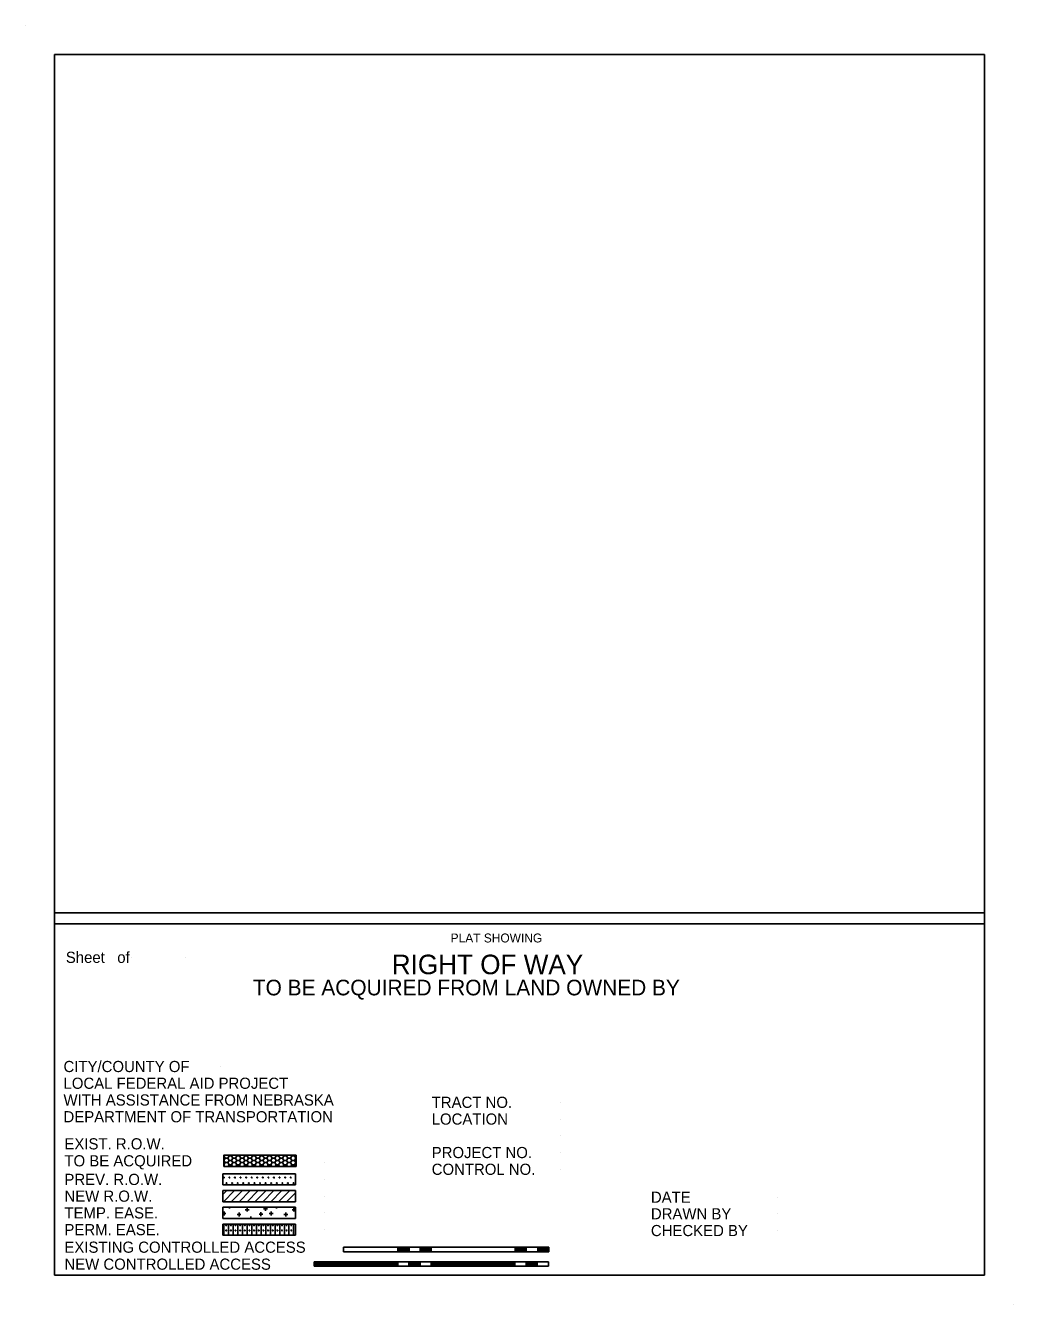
# Model space of a CAD drawing. Extents: x 18533 to 19383, y 1281 to 2381.
import ezdxf

# ---------------------------------------------------------------- set-up
doc = ezdxf.new("R2010")
doc.units = 0
doc.layers.add('Level 42', color=7, linetype='Continuous')

msp = doc.modelspace()

# ---------------------------------------------------------------- linework, layer by layer
at = {"layer": 'Level 42'}
for p, q in [((18532.7, 2381.3), (18532.7, 2381.3)), ((18557.7, 1306.4), (18557.7, 2356.3)), ((18557.7, 2356.3), (19357.7, 2356.3)), ((19357.7, 2356.3), (19357.7, 1306.4)), ((18557.7, 1618.3), (19357.7, 1618.3)), ((18557.7, 1608.7), (19357.7, 1608.7)), ((18624, 1579.9), (18624, 1579.9)), ((18670.7, 1579.9), (18670.7, 1579.9)), ((18700.8, 1486), (18700.8, 1486)), ((18993, 1455.2), (18993, 1455.2)), ((18993, 1440.8), (18993, 1440.8)), ((18993, 1426.4), (18993, 1426.4)), ((18703.2, 1409.7), (18703.2, 1400.1)), ((18703.2, 1409.7), (18765.6, 1409.7)), ((18703.2, 1409.1), (18703.3, 1409.1)), ((18703.6, 1409.7), (18703.3, 1409.1)), ((18703.3, 1409.1), (18704.4, 1407.2)), ((18707.8, 1409.1), (18706.7, 1407.2)), ((18707.4, 1409.7), (18707.8, 1409.1)), ((18707.8, 1409.1), (18710, 1409.1)), ((18710.4, 1409.7), (18710, 1409.1)), ((18710, 1409.1), (18711.2, 1407.2)), ((18714.5, 1409.1), (18713.4, 1407.2)), ((18714.2, 1409.7), (18714.5, 1409.1)), ((18714.5, 1409.1), (18716.8, 1409.1)), ((18717.1, 1409.7), (18716.8, 1409.1)), ((18716.8, 1409.1), (18717.9, 1407.2)), ((18721.3, 1409.1), (18720.2, 1407.2)), ((18720.9, 1409.7), (18721.3, 1409.1)), ((18721.3, 1409.1), (18723.5, 1409.1)), ((18723.9, 1409.7), (18723.5, 1409.1)), ((18723.5, 1409.1), (18724.7, 1407.2)), ((18728, 1409.1), (18726.9, 1407.2)), ((18727.7, 1409.7), (18728, 1409.1)), ((18728, 1409.1), (18730.3, 1409.1)), ((18730.6, 1409.7), (18730.3, 1409.1)), ((18730.3, 1409.1), (18731.4, 1407.2)), ((18734.8, 1409.1), (18733.7, 1407.2)), ((18734.4, 1409.7), (18734.8, 1409.1)), ((18734.8, 1409.1), (18737, 1409.1)), ((18737.4, 1409.7), (18737, 1409.1)), ((18737, 1409.1), (18738.2, 1407.2)), ((18741.5, 1409.1), (18740.4, 1407.2)), ((18741.2, 1409.7), (18741.5, 1409.1)), ((18741.5, 1409.1), (18743.8, 1409.1)), ((18744.1, 1409.7), (18743.8, 1409.1)), ((18743.8, 1409.1), (18744.9, 1407.2)), ((18748.3, 1409.1), (18747.2, 1407.2)), ((18747.9, 1409.7), (18748.3, 1409.1)), ((18748.3, 1409.1), (18750.5, 1409.1)), ((18750.9, 1409.7), (18750.5, 1409.1)), ((18750.5, 1409.1), (18751.7, 1407.2)), ((18755, 1409.1), (18753.9, 1407.2)), ((18754.7, 1409.7), (18755, 1409.1)), ((18755, 1409.1), (18757.3, 1409.1)), ((18757.6, 1409.7), (18757.3, 1409.1)), ((18757.3, 1409.1), (18758.4, 1407.2)), ((18761.8, 1409.1), (18760.7, 1407.2)), ((18761.4, 1409.7), (18761.8, 1409.1)), ((18761.8, 1409.1), (18764, 1409.1)), ((18764.4, 1409.7), (18764, 1409.1)), ((18764, 1409.1), (18765.2, 1407.2)), ((18765.6, 1409.7), (18765.6, 1400.1)), ((18993, 1412), (18993, 1412)), ((18703.2, 1405.2), (18703.3, 1405.2)), ((18703.2, 1401.3), (18703.3, 1401.3)), ((18703.2, 1400.1), (18765.6, 1400.1)), ((18704.4, 1407.2), (18703.3, 1405.2)), ((18703.3, 1405.2), (18704.4, 1403.3)), ((18704.4, 1403.3), (18703.3, 1401.3)), ((18703.3, 1401.3), (18704, 1400.1)), ((18704.4, 1407.2), (18706.7, 1407.2)), ((18704.4, 1403.3), (18706.7, 1403.3)), ((18706.7, 1407.2), (18707.8, 1405.2)), ((18707.8, 1405.2), (18706.7, 1403.3)), ((18706.7, 1403.3), (18707.8, 1401.3)), ((18707.1, 1400.1), (18707.8, 1401.3)), ((18707.8, 1405.2), (18710, 1405.2)), ((18707.8, 1401.3), (18710, 1401.3)), ((18711.2, 1407.2), (18710, 1405.2)), ((18710, 1405.2), (18711.2, 1403.3)), ((18711.2, 1403.3), (18710, 1401.3)), ((18710, 1401.3), (18710.7, 1400.1)), ((18711.2, 1407.2), (18713.4, 1407.2)), ((18711.2, 1403.3), (18713.4, 1403.3)), ((18713.4, 1407.2), (18714.5, 1405.2)), ((18714.5, 1405.2), (18713.4, 1403.3)), ((18713.4, 1403.3), (18714.5, 1401.3)), ((18713.8, 1400.1), (18714.5, 1401.3)), ((18714.5, 1405.2), (18716.8, 1405.2)), ((18714.5, 1401.3), (18716.8, 1401.3)), ((18717.9, 1407.2), (18716.8, 1405.2)), ((18716.8, 1405.2), (18717.9, 1403.3)), ((18717.9, 1403.3), (18716.8, 1401.3)), ((18716.8, 1401.3), (18717.5, 1400.1)), ((18717.9, 1407.2), (18720.2, 1407.2)), ((18717.9, 1403.3), (18720.2, 1403.3)), ((18720.2, 1407.2), (18721.3, 1405.2)), ((18721.3, 1405.2), (18720.2, 1403.3)), ((18720.2, 1403.3), (18721.3, 1401.3)), ((18720.6, 1400.1), (18721.3, 1401.3)), ((18721.3, 1405.2), (18723.5, 1405.2)), ((18721.3, 1401.3), (18723.5, 1401.3)), ((18724.7, 1407.2), (18723.5, 1405.2)), ((18723.5, 1405.2), (18724.7, 1403.3)), ((18724.7, 1403.3), (18723.5, 1401.3)), ((18723.5, 1401.3), (18724.2, 1400.1)), ((18724.7, 1407.2), (18726.9, 1407.2)), ((18724.7, 1403.3), (18726.9, 1403.3)), ((18726.9, 1407.2), (18728, 1405.2)), ((18728, 1405.2), (18726.9, 1403.3)), ((18726.9, 1403.3), (18728, 1401.3)), ((18727.3, 1400.1), (18728, 1401.3)), ((18728, 1405.2), (18730.3, 1405.2)), ((18728, 1401.3), (18730.3, 1401.3)), ((18731.4, 1407.2), (18730.3, 1405.2)), ((18730.3, 1405.2), (18731.4, 1403.3)), ((18731.4, 1403.3), (18730.3, 1401.3)), ((18730.3, 1401.3), (18731, 1400.1)), ((18731.4, 1407.2), (18733.7, 1407.2)), ((18731.4, 1403.3), (18733.7, 1403.3)), ((18733.7, 1407.2), (18734.8, 1405.2)), ((18734.8, 1405.2), (18733.7, 1403.3)), ((18733.7, 1403.3), (18734.8, 1401.3)), ((18734.1, 1400.1), (18734.8, 1401.3)), ((18734.8, 1405.2), (18737, 1405.2)), ((18734.8, 1401.3), (18737, 1401.3)), ((18738.2, 1407.2), (18737, 1405.2)), ((18737, 1405.2), (18738.2, 1403.3)), ((18738.2, 1403.3), (18737, 1401.3)), ((18737, 1401.3), (18737.7, 1400.1)), ((18738.2, 1407.2), (18740.4, 1407.2)), ((18738.2, 1403.3), (18740.4, 1403.3)), ((18740.4, 1407.2), (18741.5, 1405.2)), ((18741.5, 1405.2), (18740.4, 1403.3)), ((18740.4, 1403.3), (18741.5, 1401.3)), ((18740.8, 1400.1), (18741.5, 1401.3)), ((18741.5, 1405.2), (18743.8, 1405.2)), ((18741.5, 1401.3), (18743.8, 1401.3)), ((18744.9, 1407.2), (18743.8, 1405.2)), ((18743.8, 1405.2), (18744.9, 1403.3)), ((18744.9, 1403.3), (18743.8, 1401.3)), ((18743.8, 1401.3), (18744.5, 1400.1)), ((18744.9, 1407.2), (18747.2, 1407.2)), ((18744.9, 1403.3), (18747.2, 1403.3)), ((18747.2, 1407.2), (18748.3, 1405.2)), ((18748.3, 1405.2), (18747.2, 1403.3)), ((18747.2, 1403.3), (18748.3, 1401.3)), ((18747.6, 1400.1), (18748.3, 1401.3)), ((18748.3, 1405.2), (18750.5, 1405.2)), ((18748.3, 1401.3), (18750.5, 1401.3)), ((18751.7, 1407.2), (18750.5, 1405.2)), ((18750.5, 1405.2), (18751.7, 1403.3)), ((18751.7, 1403.3), (18750.5, 1401.3)), ((18750.5, 1401.3), (18751.2, 1400.1)), ((18751.7, 1407.2), (18753.9, 1407.2)), ((18751.7, 1403.3), (18753.9, 1403.3)), ((18753.9, 1407.2), (18755, 1405.2)), ((18755, 1405.2), (18753.9, 1403.3)), ((18753.9, 1403.3), (18755, 1401.3)), ((18754.3, 1400.1), (18755, 1401.3)), ((18755, 1405.2), (18757.3, 1405.2)), ((18755, 1401.3), (18757.3, 1401.3)), ((18758.4, 1407.2), (18757.3, 1405.2)), ((18757.3, 1405.2), (18758.4, 1403.3)), ((18758.4, 1403.3), (18757.3, 1401.3)), ((18757.3, 1401.3), (18758, 1400.1)), ((18758.4, 1407.2), (18760.7, 1407.2)), ((18758.4, 1403.3), (18760.7, 1403.3)), ((18760.7, 1407.2), (18761.8, 1405.2)), ((18761.8, 1405.2), (18760.7, 1403.3)), ((18760.7, 1403.3), (18761.8, 1401.3)), ((18761.1, 1400.1), (18761.8, 1401.3)), ((18761.8, 1405.2), (18764, 1405.2)), ((18761.8, 1401.3), (18764, 1401.3)), ((18765.2, 1407.2), (18764, 1405.2)), ((18764, 1405.2), (18765.2, 1403.3)), ((18765.2, 1403.3), (18764, 1401.3)), ((18764, 1401.3), (18764.7, 1400.1)), ((18765.2, 1407.2), (18765.6, 1407.2)), ((18765.2, 1403.3), (18765.6, 1403.3)), ((18790.1, 1403.3), (18790.1, 1403.3)), ((18993, 1397.6), (18993, 1397.6)), ((18702.5, 1393.7), (18702.5, 1384.1)), ((18702.5, 1393.7), (18764.9, 1393.7)), ((18764.9, 1393.7), (18764.9, 1384.1)), ((18790.1, 1388.9), (18790.1, 1388.9)), ((18702.5, 1384.1), (18764.9, 1384.1)), ((18764.9, 1379.3), (18702.5, 1379.3)), ((18702.5, 1379.3), (18702.5, 1369.7)), ((18764.9, 1369.7), (18764.9, 1379.3)), ((18764.9, 1369.7), (18702.5, 1369.7)), ((18764.9, 1364.9), (18702.5, 1364.9)), ((18702.5, 1364.9), (18702.5, 1355.3)), ((18723.3, 1361.2), (18723.3, 1364.5)), ((18763.7, 1361.2), (18763.7, 1364.5)), ((18764.9, 1355.3), (18764.9, 1364.9)), ((18790.1, 1374.5), (18790.1, 1374.5)), ((19179.5, 1373.6), (19179.5, 1373.6)), ((18764.9, 1355.3), (18702.5, 1355.3)), ((18703.6, 1357.8), (18703.6, 1361.2)), ((18714.7, 1358.7), (18718, 1358.7)), ((18716.4, 1357), (18716.4, 1360.3)), ((18721.6, 1362.8), (18725, 1362.8)), ((18725, 1355.3), (18728.3, 1355.3)), ((18726.6, 1355.3), (18726.6, 1357)), ((18733.6, 1358.9), (18736.9, 1358.9)), ((18735.3, 1357.2), (18735.3, 1360.6)), ((18737.4, 1363.7), (18740.8, 1363.7)), ((18742.3, 1359.5), (18745.7, 1359.5)), ((18744, 1357.8), (18744, 1361.2)), ((18755.1, 1358.7), (18758.5, 1358.7)), ((18756.8, 1357), (18756.8, 1360.3)), ((18790.1, 1360.1), (18790.1, 1360.1)), ((19179.5, 1359.3), (19179.5, 1359.3)), ((18702.5, 1350.5), (18702.5, 1340.9)), ((18702.5, 1350.5), (18764.9, 1350.5)), ((18703.4, 1340.9), (18703.4, 1350.5)), ((18707.4, 1340.9), (18707.4, 1350.5)), ((18711.4, 1340.9), (18711.4, 1350.5)), ((18715.4, 1340.9), (18715.4, 1350.5)), ((18719.4, 1340.9), (18719.4, 1350.5)), ((18723.4, 1340.9), (18723.4, 1350.5)), ((18727.4, 1340.9), (18727.4, 1350.5)), ((18731.4, 1340.9), (18731.4, 1350.5)), ((18735.4, 1340.9), (18735.4, 1350.5)), ((18739.4, 1340.9), (18739.4, 1350.5)), ((18743.4, 1340.9), (18743.4, 1350.5)), ((18747.4, 1340.9), (18747.4, 1350.5)), ((18751.4, 1340.9), (18751.4, 1350.5)), ((18755.4, 1340.9), (18755.4, 1350.5)), ((18759.4, 1340.9), (18759.4, 1350.5)), ((18763.4, 1340.9), (18763.4, 1350.5)), ((18764.9, 1350.5), (18764.9, 1340.9)), ((18790.1, 1345.7), (18790.1, 1345.7)), ((19179.5, 1344.9), (19179.5, 1344.9)), ((18764.9, 1340.9), (18702.5, 1340.9)), ((18806.2, 1330.6), (18806.2, 1326.7)), ((18853.1, 1326.7), (18853.1, 1330.6)), ((18862.7, 1330.6), (18862.7, 1326.8)), ((18872.2, 1326.7), (18872.2, 1330.6)), ((18881.8, 1326.7), (18881.8, 1330.6)), ((18953.9, 1326.7), (18953.9, 1330.6)), ((18963.6, 1326.7), (18963.6, 1330.5)), ((18973.4, 1326.7), (18973.4, 1330.6)), ((18983, 1330.6), (18983, 1326.7)), ((18781, 1318), (18781, 1314.2)), ((18853, 1314.2), (18853, 1318)), ((18862.6, 1318), (18862.6, 1314.2)), ((18872.2, 1314.2), (18872.2, 1318)), ((18881.8, 1318), (18881.8, 1314.2)), ((18953.8, 1314.2), (18953.8, 1318)), ((18963.4, 1318), (18963.4, 1314.2)), ((18973, 1314.2), (18973, 1318)), ((18982.6, 1318), (18982.6, 1314.2)), ((19357.7, 1306.4), (18557.7, 1306.4)), ((19382.7, 1281.4), (19382.7, 1281.4))]:
    msp.add_line(p, q, dxfattribs=at)
for points in [[(18703, 1390.2), (18703, 1390.7), (18703.5, 1390.7), (18703.5, 1390.2)], [(18707.8, 1390.2), (18707.8, 1390.7), (18708.3, 1390.7), (18708.3, 1390.2)], [(18712.6, 1390.2), (18712.6, 1390.7), (18713.1, 1390.7), (18713.1, 1390.2)], [(18717.4, 1390.2), (18717.4, 1390.7), (18717.9, 1390.7), (18717.9, 1390.2)], [(18722.2, 1390.2), (18722.2, 1390.7), (18722.7, 1390.7), (18722.7, 1390.2)], [(18727, 1390.2), (18727, 1390.7), (18727.5, 1390.7), (18727.5, 1390.2)], [(18731.8, 1390.2), (18731.8, 1390.7), (18732.3, 1390.7), (18732.3, 1390.2)], [(18736.6, 1390.2), (18736.6, 1390.7), (18737.1, 1390.7), (18737.1, 1390.2)], [(18741.4, 1390.2), (18741.4, 1390.7), (18741.9, 1390.7), (18741.9, 1390.2)], [(18746.2, 1390.2), (18746.2, 1390.7), (18746.7, 1390.7), (18746.7, 1390.2)], [(18751, 1390.2), (18751, 1390.7), (18751.5, 1390.7), (18751.5, 1390.2)], [(18755.8, 1390.2), (18755.8, 1390.7), (18756.3, 1390.7), (18756.3, 1390.2)], [(18760.6, 1390.2), (18760.6, 1390.7), (18761.1, 1390.7), (18761.1, 1390.2)], [(18705.4, 1385.4), (18705.4, 1385.9), (18705.9, 1385.9), (18705.9, 1385.4)], [(18710.2, 1385.4), (18710.2, 1385.9), (18710.7, 1385.9), (18710.7, 1385.4)], [(18715, 1385.4), (18715, 1385.9), (18715.5, 1385.9), (18715.5, 1385.4)], [(18719.8, 1385.4), (18719.8, 1385.9), (18720.3, 1385.9), (18720.3, 1385.4)], [(18724.6, 1385.4), (18724.6, 1385.9), (18725.1, 1385.9), (18725.1, 1385.4)], [(18729.4, 1385.4), (18729.4, 1385.9), (18729.9, 1385.9), (18729.9, 1385.4)], [(18734.2, 1385.4), (18734.2, 1385.9), (18734.7, 1385.9), (18734.7, 1385.4)], [(18739, 1385.4), (18739, 1385.9), (18739.5, 1385.9), (18739.5, 1385.4)], [(18743.8, 1385.4), (18743.8, 1385.9), (18744.3, 1385.9), (18744.3, 1385.4)], [(18748.6, 1385.4), (18748.6, 1385.9), (18749.1, 1385.9), (18749.1, 1385.4)], [(18753.4, 1385.4), (18753.4, 1385.9), (18753.9, 1385.9), (18753.9, 1385.4)], [(18758.2, 1385.4), (18758.2, 1385.9), (18758.7, 1385.9), (18758.7, 1385.4)], [(18763, 1385.4), (18763, 1385.9), (18763.5, 1385.9), (18763.5, 1385.4)]]:
    msp.add_lwpolyline(points, close=True, dxfattribs=at)
for points in [[(18702.5, 1376), (18705.8, 1379.3)], [(18703, 1369.7), (18712.6, 1379.3)], [(18709.7, 1369.7), (18719.3, 1379.3)], [(18716.5, 1369.7), (18726.1, 1379.3)], [(18723.3, 1369.7), (18732.9, 1379.3)], [(18730.1, 1369.7), (18739.7, 1379.3)], [(18736.9, 1369.7), (18746.5, 1379.3)], [(18743.7, 1369.7), (18753.3, 1379.3)], [(18750.5, 1369.7), (18760.1, 1379.3)], [(18757.3, 1369.7), (18764.9, 1377.3)], [(18708.2, 1363.9), (18708.2, 1364.9)], [(18739.1, 1362), (18739.1, 1364.9)], [(18748.7, 1363.9), (18748.7, 1364.9)], [(18764, 1369.7), (18764.9, 1370.5)], [(18702.5, 1359.5), (18705.2, 1359.5)], [(18762, 1362.8), (18764.9, 1362.8)], [(18806.2, 1330.6), (18983, 1330.6)], [(18806.2, 1326.7), (18983, 1326.7)], [(18853.1, 1330.4), (18862.7, 1330.4)], [(18853.1, 1330.2), (18862.7, 1330.2)], [(18853.1, 1330), (18862.7, 1330)], [(18853.1, 1329.7), (18862.7, 1329.7)], [(18853.1, 1329.5), (18862.7, 1329.5)], [(18853.1, 1329.2), (18862.7, 1329.2)], [(18853.1, 1328.9), (18862.7, 1328.9)], [(18853.1, 1328.6), (18862.7, 1328.6)], [(18853.1, 1328.3), (18862.7, 1328.3)], [(18853.1, 1328), (18862.7, 1328)], [(18853.1, 1327.7), (18862.7, 1327.7)], [(18853.1, 1327.3), (18862.7, 1327.3)], [(18853.1, 1326.9), (18862.7, 1326.9)], [(18872.2, 1330.5), (18881.8, 1330.5)], [(18872.2, 1330.3), (18881.8, 1330.3)], [(18872.2, 1330.2), (18881.8, 1330.2)], [(18872.2, 1330.1), (18881.8, 1330.1)], [(18872.2, 1330), (18881.8, 1330)], [(18872.2, 1329.8), (18881.8, 1329.8)], [(18872.2, 1329.7), (18881.8, 1329.7)], [(18872.2, 1329.6), (18881.8, 1329.6)], [(18872.2, 1329.4), (18881.8, 1329.4)], [(18872.2, 1329.3), (18881.8, 1329.3)], [(18872.2, 1329.2), (18881.8, 1329.2)], [(18872.2, 1329), (18881.8, 1329)], [(18872.2, 1328.9), (18881.8, 1328.9)], [(18872.2, 1328.8), (18881.8, 1328.8)], [(18872.2, 1328.6), (18881.8, 1328.6)], [(18872.2, 1328.5), (18881.8, 1328.5)], [(18872.2, 1328.3), (18881.8, 1328.3)], [(18872.2, 1328.2), (18881.8, 1328.2)], [(18872.2, 1328.1), (18881.8, 1328.1)], [(18872.2, 1327.9), (18881.8, 1327.9)], [(18872.2, 1327.7), (18881.8, 1327.7)], [(18872.2, 1327.6), (18881.8, 1327.6)], [(18872.2, 1327.4), (18881.8, 1327.4)], [(18872.2, 1327.2), (18881.8, 1327.2)], [(18872.2, 1327), (18881.8, 1327)], [(18872.2, 1326.9), (18881.8, 1326.9)], [(18954, 1330.3), (18963.6, 1330.3)], [(18954, 1329.9), (18963.6, 1329.9)], [(18954, 1329.6), (18963.6, 1329.6)], [(18954, 1329.2), (18963.6, 1329.2)], [(18954, 1328.7), (18963.6, 1328.7)], [(18954, 1328.3), (18963.6, 1328.3)], [(18954, 1327.9), (18963.6, 1327.9)], [(18954, 1327.5), (18963.6, 1327.5)], [(18954, 1327.1), (18963.6, 1327.1)], [(18973.4, 1330.3), (18983, 1330.3)], [(18973.4, 1330), (18983, 1330)], [(18973.4, 1329.8), (18983, 1329.8)], [(18973.4, 1329.4), (18983, 1329.4)], [(18973.4, 1329.1), (18983, 1329.1)], [(18973.4, 1328.8), (18983, 1328.8)], [(18973.4, 1328.5), (18983, 1328.5)], [(18973.4, 1328.1), (18983, 1328.1)], [(18973.4, 1327.7), (18983, 1327.7)], [(18973.4, 1327.4), (18983, 1327.4)], [(18973.4, 1327.1), (18983, 1327.1)], [(18781, 1318), (18982.6, 1318)], [(18781, 1317.5), (18853, 1317.5)], [(18781, 1317), (18853, 1317)], [(18781, 1316.6), (18853, 1316.6)], [(18781, 1316.1), (18853, 1316.1)], [(18781, 1315.6), (18853, 1315.6)], [(18781, 1315.1), (18853, 1315.1)], [(18781, 1314.6), (18853, 1314.6)], [(18781, 1314.2), (18982.6, 1314.2)], [(18862.6, 1317.5), (18872.2, 1317.5)], [(18862.6, 1317), (18872.2, 1317)], [(18862.6, 1316.6), (18872.2, 1316.6)], [(18862.6, 1316.1), (18872.2, 1316.1)], [(18862.6, 1315.6), (18872.2, 1315.6)], [(18862.6, 1315.1), (18872.2, 1315.1)], [(18862.6, 1314.6), (18872.2, 1314.6)], [(18881.8, 1317.5), (18953.8, 1317.5)], [(18881.8, 1317), (18953.8, 1317)], [(18881.8, 1316.6), (18953.8, 1316.6)], [(18881.8, 1316.1), (18953.8, 1316.1)], [(18881.8, 1315.6), (18953.8, 1315.6)], [(18881.8, 1315.1), (18953.8, 1315.1)], [(18881.8, 1314.6), (18953.8, 1314.6)], [(18963.4, 1317.5), (18973, 1317.5)], [(18963.4, 1317), (18973, 1317)], [(18963.4, 1316.6), (18973, 1316.6)], [(18963.4, 1316.1), (18973, 1316.1)], [(18963.4, 1315.6), (18973, 1315.6)], [(18963.4, 1315.1), (18973, 1315.1)], [(18963.4, 1314.6), (18973, 1314.6)], [(18982.6, 1317.5), (18982.6, 1317.5)], [(18982.6, 1317), (18982.6, 1317)], [(18982.6, 1316.6), (18982.6, 1316.6)], [(18982.6, 1316.1), (18982.6, 1316.1)], [(18982.6, 1315.6), (18982.6, 1315.6)], [(18982.6, 1315.1), (18982.6, 1315.1)], [(18982.6, 1314.6), (18982.6, 1314.6)]]:
    msp.add_lwpolyline(points, dxfattribs=at)
for centre in [(18705.4, 1349.4), (18705.4, 1345), (18709.4, 1349.4), (18709.4, 1345), (18713.4, 1349.4), (18713.4, 1345), (18717.4, 1349.4), (18717.4, 1345), (18721.4, 1349.4), (18721.4, 1345), (18725.4, 1349.4), (18725.4, 1345), (18729.4, 1349.4), (18729.4, 1345), (18733.4, 1349.4), (18733.4, 1345), (18737.4, 1349.4), (18737.4, 1345), (18741.4, 1349.4), (18741.4, 1345), (18745.4, 1349.4), (18745.4, 1345), (18749.4, 1349.4), (18749.4, 1345), (18753.4, 1349.4), (18753.4, 1345), (18757.4, 1349.4), (18757.4, 1345), (18761.4, 1349.4), (18761.4, 1345)]:
    msp.add_circle(centre, 0.364, dxfattribs=at)

# ---------------------------------------------------------------- texts
for s, height, p in [('PLAT SHOWING', 7.68, (18898.5, 1592.7)), ('Sheet   of', 9.6, (18567.4, 1575.1)), ('RIGHT OF WAY', 16.799, (18847.8, 1565.4)), ('TO BE ACQUIRED FROM LAND OWNED BY', 13.439, (18728.3, 1547.2)), ('CITY/COUNTY OF', 9.6, (18565.4, 1481.2)), ('LOCAL FEDERAL AID PROJECT', 9.6, (18565.4, 1466.8)), ('WITH ASSISTANCE FROM NEBRASKA', 9.6, (18565.4, 1452.4)), ('TRACT NO.', 9.6, (18882.2, 1450.4)), ('DEPARTMENT OF TRANSPORTATION', 9.6, (18565.4, 1438)), ('LOCATION', 9.6, (18882.2, 1436)), ('EXIST. R.O.W. ', 9.6, (18566.2, 1414.7)), ('TO BE ACQUIRED', 9.6, (18566.2, 1400.1)), ('PROJECT NO.', 9.6, (18882.2, 1407.2)), ('CONTROL NO.', 9.6, (18882.2, 1392.8)), ('PREV. R.O.W.', 9.6, (18566.2, 1384.1)), ('NEW R.O.W.', 9.6, (18566.2, 1369.7)), ('DATE', 9.6, (19070.8, 1368.8)), ('TEMP. EASE.', 9.6, (18566.2, 1355.3)), ('DRAWN BY', 9.6, (19070.8, 1354.5)), ('PERM. EASE.', 9.6, (18566.2, 1340.9)), ('CHECKED BY', 9.6, (19070.8, 1340.1)), ('EXISTING CONTROLLED ACCESS', 9.6, (18566.2, 1325.8)), ('NEW CONTROLLED ACCESS', 9.6, (18566.2, 1311.2))]:
    msp.add_text(s, height=height, dxfattribs=at).set_placement(p)

doc.saveas('drawing.dxf')
